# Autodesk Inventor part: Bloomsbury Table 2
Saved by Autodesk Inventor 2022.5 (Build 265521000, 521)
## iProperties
Created: 2024-09
Part Number: Bloomsbury Table 2
Material: Generic
Document SubType Name: Modeling
Designer: AdminForWorker
Density: 1 g/cm^3
Appearance: Default
Title: Bloomsbury Table 2 v2
Author: AdminForWorker
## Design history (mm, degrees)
feature "Body1"
feature "Body2"
feature "Body3"
feature "Body4"
feature "Body7"
feature "Body11"
body "Solid1"
body "Solid2"
body "Solid3"
body "Solid4"
body "Solid5"
body "Solid6"
